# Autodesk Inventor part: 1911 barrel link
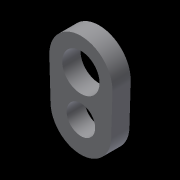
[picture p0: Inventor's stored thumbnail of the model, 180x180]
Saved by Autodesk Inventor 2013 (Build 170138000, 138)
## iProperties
Created: 2013-01
Part Number: 1911 barrel link
Material: Generic
Document SubType Name: Modeling
Designer: John
Density: 1 g/cm^3
Author: John
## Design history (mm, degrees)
sketch "Sketch1"
  geometry: L1 (-4.395, -0.133)-(-4.222, -5.843); L2 (4.395, -0.133)-(4.222, -5.843); C1 r 2.597 at (0, 0) reference; C2 r 1.988 at (0, -5.715); A1 r 4.224 centre (0, -5.715) between (-4.222, -5.843) and (4.222, -5.843); A2 r 4.397 centre (0, 0) between (4.395, -0.133) and (-4.395, -0.133); 1 further point
  constraints: 4 centre point, 4 end point, 4 point on circle, 4 tangent, 3 coincident, 2 other
  dimensions: "d9" = 3.9751 diameter of C2
extrude "Extrusion2" new body sketch "Sketch1" distance "d7" = 2.54; taper "d8" = 0 deg
body "Solid2"
